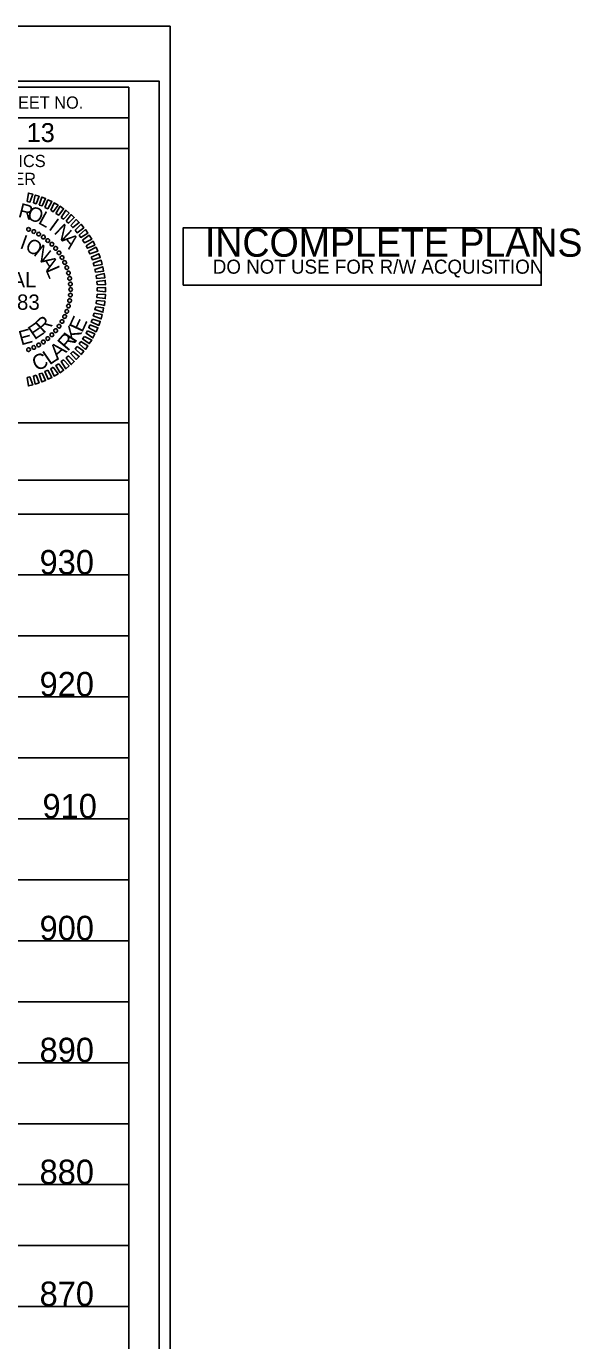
# Model space of a CAD drawing. Extents: x 1648862 to 1650715, y 820691 to 821791.
# Drawn here: x 1650487 to 1650715, y 821252 to 821791 of the extents above; entities that cross this region are included whole.
import ezdxf

# ---------------------------------------------------------------- set-up
doc = ezdxf.new("R2010")
doc.units = 0
for name, color, linetype in [('Default', 7, 'Continuous'), ('Exist Vertical Profile Vertical Axis Label', 7, 'Continuous'), ('Old_Level_2', 7, 'Continuous'), ('Sheet Cutting Line CELL', 7, 'Continuous'), ('Sheet Data Field CELL', 7, 'Continuous'), ('Sheet DOT Grid CELL', 7, 'Continuous'), ('Sheet Plot Border Inside CELL', 7, 'Continuous'), ('Sheet Plot Border Outside CELL', 7, 'Continuous'), ('Sheet Profile CELL', 7, 'Continuous'), ('Sheet Profile Grid Major CELL', 7, 'Continuous'), ('Sheet Profile Grid Middle CELL', 7, 'Continuous'), ('Sheet Sticker Exception Certification CELL', 7, 'Continuous'), ('Sheet Sticker Incomplete CELL', 7, 'Continuous')]:
    doc.layers.add(name, color=color, linetype=linetype)

msp = doc.modelspace()

# ---------------------------------------------------------------- linework, layer by layer
at = {"layer": 'Old_Level_2'}
for p, q in [((1650488.21, 821707.77), (1650488.21, 821707.77)), ((1650490.32, 821706.87), (1650490.32, 821706.87)), ((1650492.38, 821705.86), (1650492.38, 821705.86)), ((1650494.28, 821704.58), (1650494.28, 821704.58)), ((1650496.14, 821703.2), (1650496.14, 821703.2)), ((1650497.79, 821701.66), (1650497.79, 821701.66)), ((1650499.38, 821699.96), (1650499.38, 821699.96)), ((1650500.72, 821698.16), (1650500.72, 821698.16)), ((1650501.96, 821696.19), (1650501.96, 821696.19)), ((1650503.04, 821694.17), (1650503.04, 821694.17)), ((1650503.91, 821692.09), (1650503.91, 821692.09)), ((1650504.58, 821689.91), (1650504.58, 821689.91)), ((1650505.04, 821687.62), (1650505.04, 821687.62)), ((1650505.39, 821685.37), (1650505.39, 821685.37)), ((1650505.37, 821680.77), (1650505.37, 821680.77)), ((1650505.48, 821683.07), (1650505.48, 821683.07)), ((1650503.92, 821674.1), (1650503.92, 821674.1)), ((1650504.61, 821676.31), (1650504.61, 821676.31)), ((1650505.04, 821678.52), (1650505.04, 821678.52)), ((1650500.73, 821668.03), (1650500.73, 821668.03)), ((1650502, 821669.94), (1650502, 821669.94)), ((1650503.01, 821672), (1650503.01, 821672)), ((1650496.11, 821662.93), (1650496.11, 821662.93)), ((1650497.81, 821664.53), (1650497.81, 821664.53)), ((1650499.35, 821666.18), (1650499.35, 821666.18)), ((1650488.24, 821658.4), (1650488.24, 821658.4)), ((1650490.32, 821659.28), (1650490.32, 821659.28)), ((1650492.34, 821660.36), (1650492.34, 821660.36)), ((1650494.3, 821661.59), (1650494.3, 821661.59))]:
    msp.add_line(p, q, dxfattribs=at)
for points in [[(1650487.65, 821719.21), (1650488.11, 821722.62), (1650489.9, 821722.23), (1650488.75, 821718.97)], [(1650490.17, 821718.58), (1650490.9, 821721.83), (1650492.53, 821721.34), (1650491.27, 821718.23)], [(1650492.54, 821717.68), (1650493.68, 821720.99), (1650495.16, 821720.39), (1650493.75, 821717.33)], [(1650494.91, 821716.72), (1650496.16, 821719.83), (1650497.79, 821719.13), (1650496.07, 821716.17)], [(1650497.33, 821715.56), (1650498.69, 821718.57), (1650500.28, 821717.71), (1650498.34, 821714.95)], [(1650499.4, 821714.19), (1650501.17, 821717.25), (1650502.55, 821716.18), (1650500.56, 821713.58)], [(1650501.57, 821712.66), (1650503.45, 821715.57), (1650504.83, 821714.44), (1650502.57, 821711.94)], [(1650503.58, 821711.07), (1650505.68, 821713.83), (1650506.96, 821712.59), (1650504.59, 821710.3)], [(1650505.5, 821709.27), (1650507.7, 821711.77), (1650508.98, 821710.54), (1650506.3, 821708.45)], [(1650507.36, 821707.42), (1650509.72, 821709.82), (1650510.85, 821708.43), (1650508.11, 821706.39)], [(1650508.96, 821705.41), (1650511.49, 821707.65), (1650512.51, 821706.15), (1650509.61, 821704.43)], [(1650510.36, 821703.29), (1650513.1, 821705.33), (1650514.12, 821703.78), (1650511.11, 821702.26)], [(1650511.76, 821701.02), (1650514.66, 821702.9), (1650515.36, 821701.29), (1650512.41, 821700.03)], [(1650512.85, 821698.79), (1650515.9, 821700.41), (1650516.61, 821698.75), (1650513.39, 821697.65)], [(1650513.83, 821696.35), (1650516.99, 821697.76), (1650517.6, 821696.15), (1650514.37, 821695.26)], [(1650514.71, 821693.85), (1650518.03, 821695.11), (1650518.38, 821693.39), (1650515.09, 821692.76)], [(1650515.38, 821691.35), (1650518.66, 821692.4), (1650519, 821690.63), (1650515.71, 821690.26)], [(1650515.89, 821688.85), (1650519.28, 821689.64), (1650519.47, 821687.87), (1650516.13, 821687.6)], [(1650516.25, 821686.35), (1650519.64, 821686.82), (1650519.78, 821685.05), (1650516.38, 821685.09)], [(1650516.35, 821683.73), (1650519.75, 821683.95), (1650519.78, 821682.17), (1650516.37, 821682.48)], [(1650516.13, 821678.61), (1650519.48, 821678.35), (1650519.3, 821676.57), (1650515.89, 821677.35)], [(1650516.34, 821681.12), (1650519.74, 821681.07), (1650519.67, 821679.35), (1650516.26, 821679.86)], [(1650515.12, 821673.41), (1650518.37, 821672.79), (1650518.04, 821671.06), (1650514.72, 821672.31)], [(1650515.75, 821675.93), (1650519, 821675.57), (1650518.67, 821673.79), (1650515.36, 821674.83)], [(1650513.37, 821668.57), (1650516.64, 821667.42), (1650515.88, 821665.79), (1650512.87, 821667.41)], [(1650514.38, 821670.89), (1650517.64, 821670), (1650516.98, 821668.37), (1650513.82, 821669.78)], [(1650511.15, 821663.88), (1650514.11, 821662.36), (1650513.09, 821660.88), (1650510.33, 821662.92)], [(1650512.37, 821666.15), (1650515.37, 821664.89), (1650514.62, 821663.26), (1650511.76, 821665.14)], [(1650506.29, 821657.72), (1650509, 821655.63), (1650507.71, 821654.4), (1650505.47, 821656.87)], [(1650508.09, 821659.74), (1650510.84, 821657.75), (1650509.72, 821656.37), (1650507.37, 821658.79)], [(1650509.62, 821661.76), (1650512.48, 821660.03), (1650511.51, 821658.5), (1650508.96, 821660.75)], [(1650500.58, 821652.6), (1650502.56, 821649.97), (1650501.22, 821648.95), (1650499.44, 821651.96)], [(1650502.54, 821654.21), (1650504.83, 821651.74), (1650503.44, 821650.61), (1650501.56, 821653.51)], [(1650504.6, 821655.86), (1650506.94, 821653.6), (1650505.71, 821652.33), (1650503.62, 821655.12)], [(1650488.75, 821647.22), (1650489.9, 821643.95), (1650488.13, 821643.55), (1650487.65, 821646.94)], [(1650491.25, 821647.94), (1650492.5, 821644.83), (1650490.89, 821644.33), (1650490.15, 821647.56)], [(1650493.79, 821648.82), (1650495.2, 821645.82), (1650493.65, 821645.16), (1650492.49, 821648.49)], [(1650496.07, 821649.96), (1650497.8, 821647.06), (1650496.19, 821646.3), (1650494.93, 821649.47)], [(1650498.3, 821651.26), (1650500.28, 821648.47), (1650498.68, 821647.6), (1650497.32, 821650.61)]]:
    msp.add_lwpolyline(points, close=True, dxfattribs=at)
for centre, major_axis in [((1650488.2, 821707.73), (0.258, 0.708)), ((1650490.32, 821706.86), (0.318, 0.682)), ((1650492.35, 821705.8), (0.376, 0.652)), ((1650494.27, 821704.57), (0.432, 0.617)), ((1650496.09, 821703.18), (0.484, 0.577)), ((1650497.78, 821701.63), (0.532, 0.532)), ((1650499.32, 821699.95), (0.577, 0.484)), ((1650500.72, 821698.13), (0.617, 0.432)), ((1650501.95, 821696.2), (0.652, 0.376)), ((1650503, 821694.17), (0.682, 0.318)), ((1650503.88, 821692.06), (0.708, 0.258)), ((1650504.57, 821689.87), (0.727, 0.195)), ((1650505.06, 821687.64), (0.742, 0.131)), ((1650505.36, 821685.37), (0.75, 0.066)), ((1650505.06, 821678.53), (0.742, -0.131)), ((1650505.36, 821680.8), (0.75, -0.066)), ((1650505.46, 821683.09), (0.753, 0)), ((1650503.88, 821674.12), (0.708, -0.258)), ((1650504.57, 821676.3), (0.727, -0.195)), ((1650500.72, 821668.04), (0.617, -0.432)), ((1650501.95, 821669.97), (0.652, -0.376)), ((1650503, 821672), (0.682, -0.318)), ((1650494.27, 821661.6), (0.432, -0.617)), ((1650496.09, 821662.99), (0.484, -0.577)), ((1650497.78, 821664.54), (0.532, -0.532)), ((1650499.32, 821666.23), (0.577, -0.484)), ((1650488.2, 821658.44), (0.258, -0.708)), ((1650490.32, 821659.32), (0.318, -0.682)), ((1650492.35, 821660.37), (0.376, -0.652))]:
    msp.add_ellipse(centre, major_axis=major_axis, ratio=0.999708, dxfattribs=at)
at = {"layer": 'Sheet Cutting Line CELL'}
msp.add_line((1650546.28, 821791.02), (1648862.28, 821791.02), dxfattribs=at)
at = {"layer": 'Sheet DOT Grid CELL'}
for p, q in [((1650529.28, 821566.02), (1649029.28, 821566.02)), ((1650529.28, 821516.02), (1649029.28, 821516.02)), ((1650529.28, 821466.02), (1649029.28, 821466.02)), ((1650529.28, 821416.02), (1649029.28, 821416.02)), ((1650529.28, 821366.02), (1649029.28, 821366.02)), ((1650529.28, 821316.02), (1649029.28, 821316.02))]:
    msp.add_line(p, q, dxfattribs=at)
at = {"layer": 'Sheet Plot Border Inside CELL'}
msp.add_lwpolyline([(1648875.28, 820713.47), (1650541.78, 820713.47), (1650541.78, 821768.57), (1648875.28, 821768.57)], close=True, dxfattribs=at)
at = {"layer": 'Sheet Plot Border Outside CELL'}
msp.add_lwpolyline([(1648862.28, 820691.02), (1650546.28, 820691.02), (1650546.28, 821791.02), (1648862.28, 821791.02)], close=True, dxfattribs=at)
at = {"layer": 'Sheet Profile CELL'}
for p, q in [((1650329.23, 821753.47), (1650529.28, 821753.47)), ((1649029.28, 821266.02), (1650529.28, 821266.02))]:
    msp.add_line(p, q, dxfattribs=at)
for points in [[(1650529.28, 821766.02), (1649029.28, 821766.02), (1649029.28, 820716.02), (1650529.28, 820716.02)], [(1650329.23, 821766.02), (1650529.28, 821766.02), (1650529.28, 821740.97), (1650329.23, 821740.97)], [(1650429.28, 821740.97), (1650529.28, 821740.97), (1650529.28, 821628.47), (1650429.28, 821628.47)]]:
    msp.add_lwpolyline(points, close=True, dxfattribs=at)
at = {"layer": 'Sheet Profile Grid Major CELL'}
for points in [[(1650479.28, 821604.97), (1650479.28, 821266.02), (1650529.28, 821266.02), (1650529.28, 821616.02)], [(1650529.23, 821566.02), (1649029.23, 821566.02), (1649029.23, 821516.02), (1650529.23, 821516.02)], [(1650529.23, 821466.02), (1649029.23, 821466.02), (1649029.23, 821416.02), (1650529.23, 821416.02)], [(1650529.23, 821366.02), (1649029.23, 821366.02), (1649029.23, 821366.02), (1649029.23, 821316.02), (1650529.23, 821316.02)]]:
    msp.add_lwpolyline(points, dxfattribs=at)
at = {"layer": 'Sheet Profile Grid Middle CELL'}
for points in [[(1650529.23, 821591.02), (1649029.23, 821591.02), (1649029.23, 821541.02), (1650354.23, 821541.02)], [(1650354.23, 821541.02), (1650529.23, 821541.02)], [(1650354.23, 821541.02), (1650529.23, 821541.02)], [(1650529.23, 821491.02), (1649029.23, 821491.02), (1649029.23, 821441.02), (1650529.23, 821441.02)], [(1650529.23, 821391.02), (1649029.23, 821391.02), (1649029.23, 821341.02), (1650529.23, 821341.02)], [(1650529.23, 821291.02), (1649029.23, 821291.02)]]:
    msp.add_lwpolyline(points, dxfattribs=at)
at = {"layer": 'Sheet Sticker Exception Certification CELL'}
for p, q in [((1650329.23, 821628.47), (1650529.27, 821628.47)), ((1650329.23, 821628.47), (1650529.27, 821628.47)), ((1650529.27, 821628.46), (1650529.27, 821604.96)), ((1650529.27, 821628.46), (1650529.27, 821604.96)), ((1650529.27, 821604.97), (1650329.23, 821604.97)), ((1650529.27, 821604.97), (1650329.23, 821604.97))]:
    msp.add_line(p, q, dxfattribs=at)
at = {"layer": 'Sheet Sticker Incomplete CELL'}
msp.add_lwpolyline([(1650551.59, 821684.82), (1650551.59, 821708.32), (1650698.59, 821708.32), (1650698.59, 821684.82)], close=True, dxfattribs=at)

# ---------------------------------------------------------------- texts
at = {"layer": 'Default'}
for s, rotation, p in [('K', 57.024, (1650507.33, 821660.9)), ('E', 65.2198, (1650510.2, 821665.13)), ('R', 49.6233, (1650504.25, 821657.47)), ('L', 34.6689, (1650496.8, 821651.89)), ('A', 40.877, (1650500.07, 821653.97)), ('C', 25.1886, (1650491.43, 821649.42))]:
    msp.add_text(s, height=6.27, rotation=rotation, dxfattribs=at).set_placement(p)
at = {"layer": 'Exist Vertical Profile Vertical Axis Label'}
for s, p in [('930', (1650492.71, 821566.27)), ('920', (1650492.71, 821516.27)), ('910', (1650493.91, 821466.27)), ('900', (1650492.71, 821416.27)), ('890', (1650492.71, 821366.27)), ('880', (1650492.71, 821316.27)), ('870', (1650492.71, 821266.27))]:
    msp.add_text(s, height=10, dxfattribs=at).set_placement(p)
at = {"layer": 'Old_Level_2'}
for s, rotation, p in [('R', 345.6211, (1650483.63, 821712.92)), ('O', 338.4212, (1650487.14, 821712.2)), ('L', 331.2209, (1650491.78, 821710.34)), ('I', 324.0201, (1650496.06, 821707.91)), ('N', 316.8189, (1650498.33, 821706.33)), ('I', 340.1896, (1650484.27, 821700.12)), ('O', 330.8335, (1650486.37, 821699.42)), ('N', 321.4766, (1650489.91, 821697.39)), ('A', 309.6172, (1650501.47, 821703.29)), ('A', 302.7603, (1650492.94, 821694.73)), ('L', 293.4009, (1650495.04, 821691.15)), ('E', 34.1241, (1650490.63, 821662.26)), ('R', 43.4814, (1650494.3, 821664.78)), ('E', 15.4118, (1650485.12, 821660.13))]:
    msp.add_text(s, height=5.9, rotation=rotation, dxfattribs=at).set_placement(p)
for s, height, p in [('SEAL', 6.273, (1650469.96, 821683.97)), ('048883', 6.275, (1650464.78, 821674.77))]:
    msp.add_text(s, height=height, dxfattribs=at).set_placement(p)
at = {"layer": 'Sheet Data Field CELL'}
msp.add_text('13', height=7.75, dxfattribs=at).set_placement((1650487.42, 821743.57))
at = {"layer": 'Sheet Profile CELL'}
for s, p in [('SHEET NO.', (1650474.59, 821757.24)), ('HYDRAULICS', (1650452.09, 821733.29)), ('ENGINEER', (1650456.34, 821725.94))]:
    msp.add_text(s, height=5, dxfattribs=at).set_placement(p)
at = {"layer": 'Sheet Sticker Incomplete CELL'}
for s, height, p in [('INCOMPLETE PLANS', 11.52, (1650560.54, 821696.52)), ('DO NOT USE FOR R/W ACQUISITION', 5.76, (1650563.79, 821689.57))]:
    msp.add_text(s, height=height, dxfattribs=at).set_placement(p)

doc.saveas('drawing.dxf')
